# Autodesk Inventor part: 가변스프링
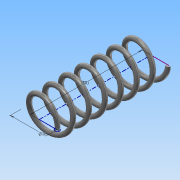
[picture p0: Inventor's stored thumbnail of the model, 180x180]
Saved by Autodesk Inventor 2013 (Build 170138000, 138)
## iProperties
Created: 2018-11
Part Number: 가변스프링
Material: 강철, 탄소
Document SubType Name: Modeling
Designer: Administrator
Density: 7.87 g/cm^3
Mass: 8.6244 g
Surface Area: 22.1693 cm^2
Volume: 1.09586 cm^3
Author: Administrator
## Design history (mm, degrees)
sketch "스케치1"
  geometry: L1 (0, 0)-(-8, 0); L2 (-8, 0)-(-8, 50); L3 (-8, 50)-(0, 50); C1 r 1 at (0, 0); 1 further point
  constraints: 6 end point, 1 centre point, 1 coincident, 1 horizontal, 1 parallel, 1 perpendicular, 1 vertical alignment
  dimensions: "d0" = 2 diameter of C1; "d1" = 16 diameter of point (0, 0) L2; "d2" = 50 distance of L1.end L2.end (derived)
feature "코일1" pitch "d3" = 10; turns "d5" = 7; dims "d4" = 50 (= d2), "d6" = 0, angle "d7" = 90 deg, angle "d8" = 90 deg, "d9" = 0, "d10" = 0
sketch "스케치2"
  geometry: C1 r 22.186 at (0, 0); 1 further point
  constraints: 1 centre point, 1 coincident
extrude "돌출1" cut sketch "스케치2" distance "d11" = 10; taper "d12" = 0 deg
node "작업 평면1"
sketch "스케치3"
  geometry: C1 r 24.048 at (-8, 0); 1 further point
  constraints: 1 centre point, 1 coincident
extrude "돌출2" cut sketch "스케치3" distance "d13" = 10; taper "d14" = 0 deg
node "솔리드1"
